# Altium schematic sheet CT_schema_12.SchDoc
size 389 x 278 mm
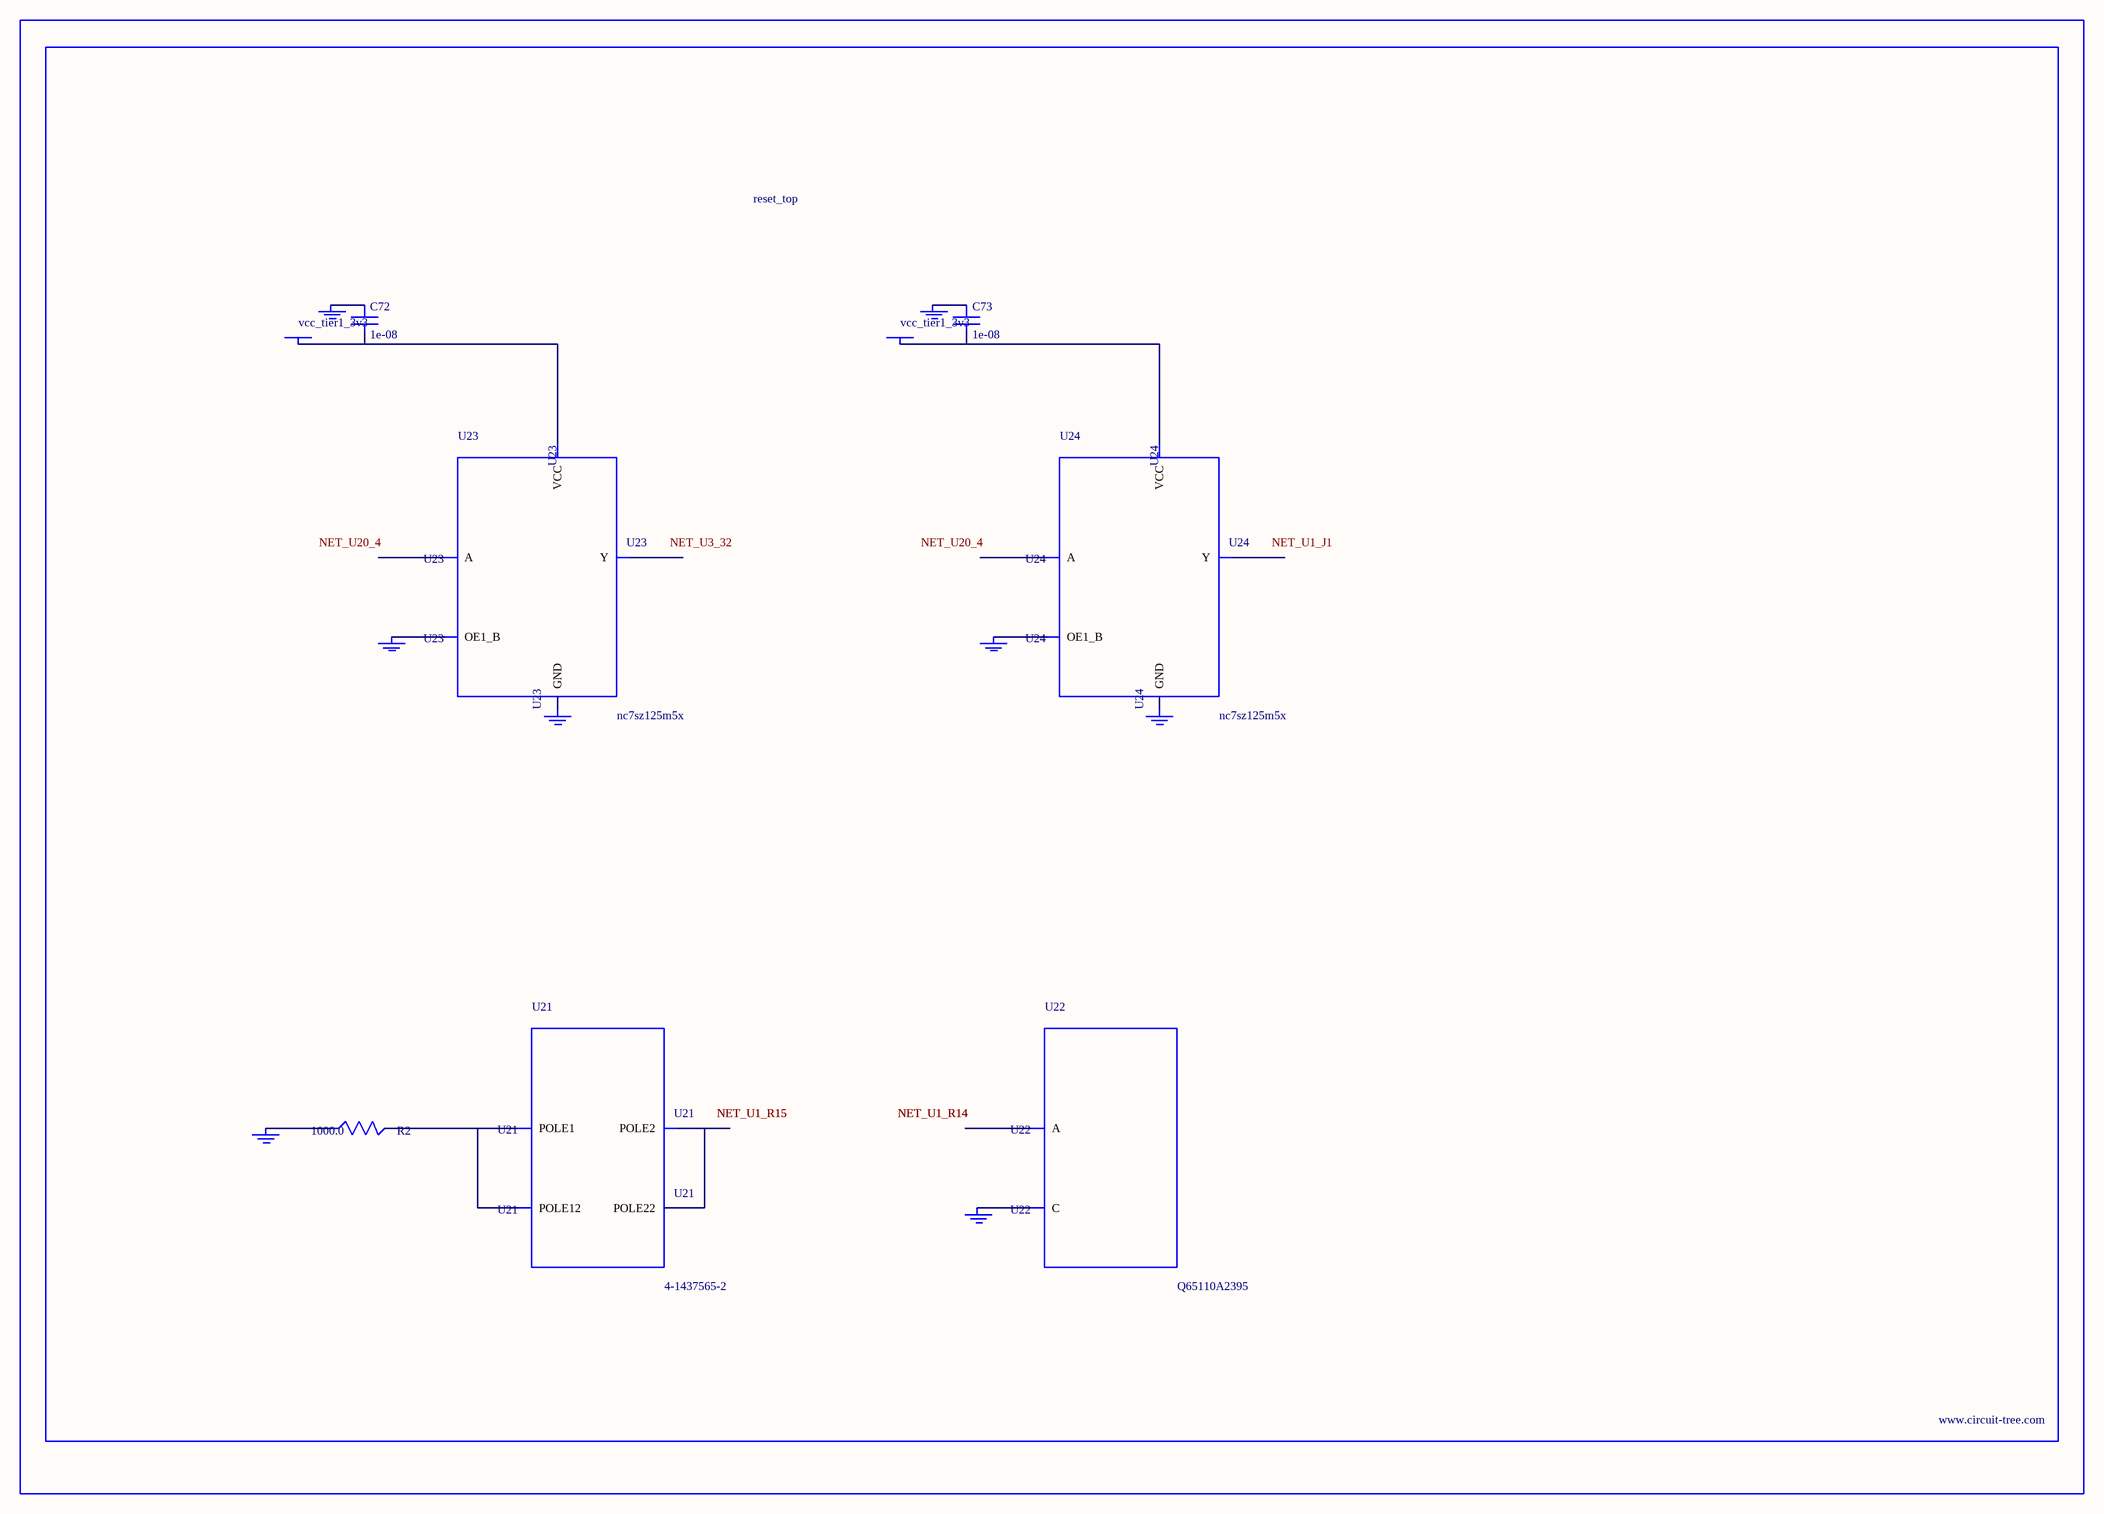
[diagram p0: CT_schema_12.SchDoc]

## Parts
BORDER11  (no value)
C72  1e-08  [C0402]
C73  1e-08  [C0402]
GND_INSTANCE_11_0  (no value)
GND_INSTANCE_11_1  (no value)
GND_INSTANCE_11_2  (no value)
GND_INSTANCE_11_3  (no value)
GND_INSTANCE_11_4  (no value)
GND_INSTANCE_11_5  (no value)
GND_INSTANCE_11_6  (no value)
GND_INSTANCE_11_7  (no value)
POWER_INSTANCE_11_0  vcc_tier1_3v3
POWER_INSTANCE_11_1  vcc_tier1_3v3
R2  1000.0  [R0603]
U21  4-1437565-2  [SW_4-1437565-2]
U22  Q65110A2395  [LGM67K-G1J2-24-Z]
U23  nc7sz125m5x  [NC7SZ125M5X]
U24  nc7sz125m5x  [NC7SZ125M5X]

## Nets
NetC72_1: C72.1 GND_INSTANCE_11_2.0(GND)
NetC72_2: C72.2 POWER_INSTANCE_11_0.0(PWR) U23.5(VCC)
NetC73_1: C73.1 GND_INSTANCE_11_5.0(GND)
NetC73_2: C73.2 POWER_INSTANCE_11_1.0(PWR) U24.5(VCC)
NetGND_INSTANCE_11_0_0: GND_INSTANCE_11_0.0(GND) R2.1
NetGND_INSTANCE_11_1_0: GND_INSTANCE_11_1.0(GND) U22.C
NetGND_INSTANCE_11_3_0: GND_INSTANCE_11_3.0(GND) U23.1(OE1_B)
NetGND_INSTANCE_11_4_0: GND_INSTANCE_11_4.0(GND) U23.3(GND)
NetGND_INSTANCE_11_6_0: GND_INSTANCE_11_6.0(GND) U24.1(OE1_B)
NetGND_INSTANCE_11_7_0: GND_INSTANCE_11_7.0(GND) U24.3(GND)
NetR2_2: R2.2 U21.1(POLE1) U21.2(POLE12)
NetU21_3: U21.3(POLE2) U21.4(POLE22)

Not connected (* = marked no-connect by the designer): U22 A; U23 2(A) 4(Y); U24 2(A) 4(Y)

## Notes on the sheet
- Labels drawn without touching a wire or pin: NET_U1_J1, NET_U3_32, NET_U20_4

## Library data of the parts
BORDER11 = BORDER_PAGE11
C72 C73 = C0402C103K3RAC
GND_INSTANCE_11_0-GND_INSTANCE_11_7 = GND
POWER_INSTANCE_11_0 POWER_INSTANCE_11_1 = PWR
R2 = RC0603JR-071KL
